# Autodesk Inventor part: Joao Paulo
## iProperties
Created: 2005-03
Part Number: Joao Paulo
Document SubType Name: Modeling
Designer: JPNoronha
Manufacturer: Standard
Standards Organization: Custom
Author: JPNoronha
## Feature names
1. Extrusion1
2. Extrusion2
3. Circular Pattern1
4. Fillet1
5. Fillet2
6. Hole1
7. Circular Pattern2
8. Revolution1
